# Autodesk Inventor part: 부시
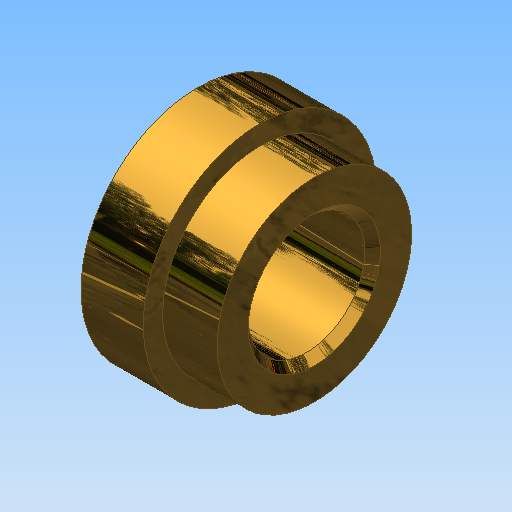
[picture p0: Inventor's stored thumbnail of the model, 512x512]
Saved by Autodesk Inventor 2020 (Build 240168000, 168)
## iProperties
Created: 2011-04
Part Number: 부시
Document SubType Name: Modeling
Density: 1 g/cm^3
Material: 일반
Appearance: 황동 - 새틴
Author: pww
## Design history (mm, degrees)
sketch "스케치1"
  geometry: L1 (0, 0)-(15, 0); L2 (0, 7.5)-(15, 7.5); L3 (15, 7.5)-(15, 12.5); L4 (15, 12.5)-(8, 12.5); L5 (8, 12.5)-(8, 15); L6 (8, 15)-(0, 15); L7 (0, 15)-(0, 7.5)
  constraints: 14 end point, 4 parallel, 2 vertical alignment, 1 horizontal, 1 perpendicular, 1 vertical
  dimensions: "d0" = 15 distance of L1.start L1.end; "d1" = 15 diameter of L2 L1; "d2" = 25 diameter of L4 L1; "d3" = 8 distance of L5.end L6.end; "d4" = 30 diameter of L6 L1
revolve "회전1" sketch "스케치1" stored, may be unused: angle "d5" = 90 deg
chamfer "모따기1" distance "d6" = 1; stored, may be unused: second distance "d7" = 2, angle "d8" = 45 deg
node "솔리드1"
